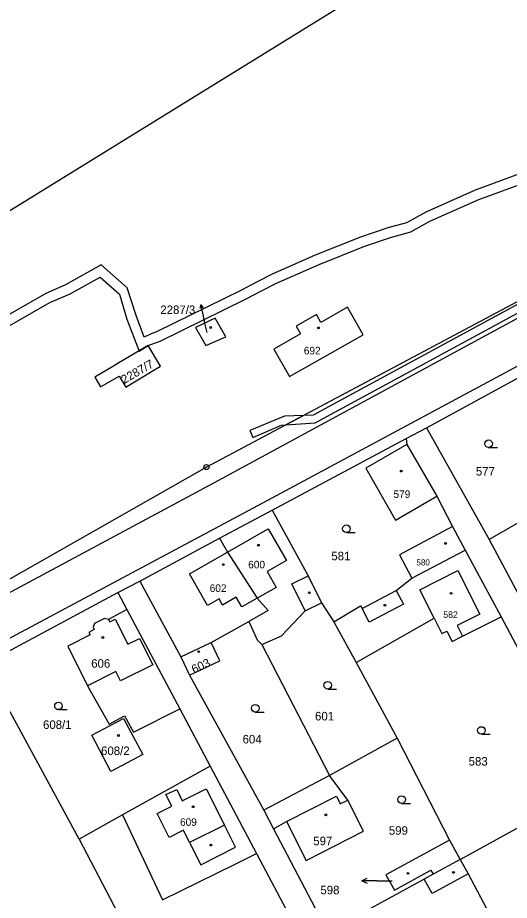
# Model space of a CAD drawing. Extents: x -504988 to -494607, y -1123820 to -1114018.
# Drawn here: x -497680.4 to -497582.5, y -1121208.2 to -1121032.5 of the extents above; entities that cross this region are included whole.
import ezdxf

# ---------------------------------------------------------------- set-up
doc = ezdxf.new("R2010")
doc.units = 0
for name, color, linetype in [('Hranice parcel', 7, 'Continuous'), ('Parcelní čísla', 7, 'Continuous'), ('Pop  PČ popisy', 7, 'Continuous'), ('Vnitřní kresba', 7, 'Continuous'), ('Věcná břemena k části', 7, 'Continuous'), ('Značky bodu BP', 7, 'Continuous'), ('Značky budov', 7, 'Continuous'), ('Značky kultur', 7, 'Continuous')]:
    doc.layers.add(name, color=color, linetype=linetype)

msp = doc.modelspace()

# ---------------------------------------------------------------- linework, layer by layer
at = {"layer": 'Hranice parcel'}
for p, q in [((-497598.99, -1121114.11), (-497574.88, -1121100.96)), ((-497603.06, -1121116.29), (-497598.99, -1121114.11)), ((-497598.99, -1121114.11), (-497586.5, -1121136.34)), ((-497629.69, -1121130.52), (-497603.06, -1121116.29)), ((-497603.06, -1121116.29), (-497602.88, -1121117.43)), ((-497602.88, -1121117.43), (-497596.93, -1121127.76)), ((-497596.93, -1121127.76), (-497593.79, -1121133.79)), ((-497571.04, -1121127.52), (-497586.5, -1121136.34)), ((-497640.18, -1121136.12), (-497629.69, -1121130.52)), ((-497593.79, -1121133.79), (-497591.32, -1121138.45)), ((-497656.09, -1121144.62), (-497640.18, -1121136.12)), ((-497586.5, -1121136.34), (-497579.58, -1121149.32)), ((-497601.88, -1121144.05), (-497591.32, -1121138.45)), ((-497591.32, -1121138.45), (-497584.13, -1121151.76)), ((-497660.42, -1121146.93), (-497656.09, -1121144.62)), ((-497656.09, -1121144.62), (-497647.9, -1121159.74)), ((-497687.08, -1121161.17), (-497660.42, -1121146.93)), ((-497660.42, -1121146.93), (-497658.64, -1121150.29)), ((-497658.64, -1121150.29), (-497648.12, -1121170.07)), ((-497619.86, -1121148.95), (-497617.46, -1121152.74)), ((-497584.13, -1121151.76), (-497566.16, -1121185.61)), ((-497641.85, -1121156.86), (-497634.37, -1121152.67)), ((-497617.46, -1121152.74), (-497613.02, -1121160.87)), ((-497647.9, -1121159.74), (-497641.85, -1121156.86)), ((-497631.8, -1121157.26), (-497618.3, -1121183.34)), ((-497668.13, -1121196.02), (-497687.08, -1121161.17)), ((-497647.9, -1121159.74), (-497646.16, -1121163.39)), ((-497613.02, -1121160.87), (-497604.82, -1121175.88)), ((-497646.16, -1121163.39), (-497631.36, -1121190.24)), ((-497648.12, -1121170.07), (-497642.06, -1121181.45)), ((-497604.82, -1121175.88), (-497618.3, -1121183.34)), ((-497604.82, -1121175.88), (-497594.41, -1121196.17)), ((-497642.06, -1121181.45), (-497659.48, -1121191.18)), ((-497642.06, -1121181.45), (-497632.82, -1121198.83)), ((-497618.3, -1121183.34), (-497631.36, -1121190.24)), ((-497592.3, -1121200.03), (-497566.16, -1121185.61)), ((-497631.36, -1121190.24), (-497629.44, -1121193.91)), ((-497659.48, -1121191.18), (-497668.13, -1121196.02)), ((-497629.44, -1121193.91), (-497618.63, -1121214.47)), ((-497668.13, -1121196.02), (-497656.18, -1121218.8)), ((-497594.41, -1121196.17), (-497592.3, -1121200.03)), ((-497632.82, -1121198.83), (-497623.17, -1121216.97)), ((-497592.3, -1121200.03), (-497597.68, -1121202.98))]:
    msp.add_line(p, q, dxfattribs=at)
for points in [[(-497161, -1120877.53), (-497162.08, -1120875.61), (-497193.91, -1120893.79), (-497205.64, -1120899.19), (-497240.26, -1120919.63), (-497250.18, -1120924.55), (-497404.22, -1121006.98), (-497504.86, -1121061.28), (-497548.64, -1121084.52), (-497630.65, -1121128.6), (-497742.3, -1121188.23), (-497831.7, -1121236.04), (-497830.39, -1121238.19)], [(-497196.93, -1120886.64), (-497265.24, -1120919.02), (-497346.92, -1120963.08), (-497519.27, -1121056.03), (-497550.25, -1121072.74), (-497642.8, -1121121.95), (-497742.1, -1121178.41), (-497789.44, -1121202.25)], [(-497820.06, -1121150.54), (-497737.19, -1121105.25), (-497683.84, -1121072.07), (-497616.03, -1121030.24), (-497577.75, -1121006.29)], [(-497629.38, -1121098.45), (-497626.29, -1121103.91), (-497611.6, -1121095.6), (-497614.69, -1121090.14), (-497620, -1121093.14), (-497620.87, -1121091.61), (-497624.94, -1121093.91), (-497624.07, -1121095.44), (-497629.38, -1121098.45)], [(-497644.95, -1121094.17), (-497642.91, -1121097.78), (-497638.93, -1121096), (-497641.09, -1121092.29), (-497644.95, -1121094.17)], [(-497660.21, -1121101.23), (-497661.29, -1121101.86), (-497664.99, -1121104.02), (-497663.86, -1121105.98), (-497660.16, -1121103.85), (-497658.82, -1121106.02), (-497657.76, -1121105.38), (-497651.95, -1121101.89), (-497654.37, -1121097.77), (-497660.21, -1121101.23)], [(-497602.88, -1121117.43), (-497611.08, -1121122.14), (-497605.13, -1121132.48), (-497596.93, -1121127.76)], [(-497629.69, -1121130.52), (-497622.54, -1121143.56), (-497619.86, -1121148.95)], [(-497593.79, -1121133.79), (-497604.35, -1121139.4), (-497601.88, -1121144.05)], [(-497640.18, -1121136.12), (-497638.63, -1121138.88), (-497632.71, -1121148.04), (-497630.52, -1121150.51), (-497634.37, -1121152.67)], [(-497617.46, -1121152.74), (-497612.12, -1121149.59), (-497611.82, -1121150.07), (-497605.01, -1121146.48), (-497601.88, -1121144.05)], [(-497658.64, -1121150.29), (-497662.28, -1121152.3), (-497663.08, -1121152.07), (-497665.07, -1121153.06), (-497665.36, -1121153.84), (-497665.13, -1121154.3), (-497666.21, -1121154.84), (-497665.95, -1121155.36), (-497670.42, -1121157.6), (-497666.47, -1121165.45), (-497662.16, -1121173.09), (-497659.08, -1121171.46), (-497657.34, -1121174.73), (-497648.12, -1121170.07)], [(-497631.8, -1121157.26), (-497627.84, -1121155.55), (-497623.14, -1121150.58), (-497619.86, -1121148.95)], [(-497613.02, -1121160.87), (-497597.45, -1121152.01), (-497595.92, -1121155.05), (-497594.97, -1121154.57), (-497593.9, -1121156.68), (-497591.79, -1121155.61), (-497584.13, -1121151.76)], [(-497634.37, -1121152.67), (-497632.72, -1121156.31), (-497631.8, -1121157.26)], [(-497646.16, -1121163.39), (-497640.11, -1121160.51), (-497641.85, -1121156.86)], [(-497665.6, -1121175.32), (-497659.29, -1121172.01), (-497655.47, -1121179.17), (-497661.81, -1121182.51), (-497665.6, -1121175.32)], [(-497629.44, -1121193.91), (-497626.87, -1121192.51), (-497622.93, -1121200.24), (-497611.51, -1121194.42), (-497614.68, -1121188.21), (-497618.3, -1121183.34)], [(-497659.48, -1121191.18), (-497651.53, -1121208.08), (-497637.11, -1121200.96), (-497632.82, -1121198.83)], [(-497594.41, -1121196.17), (-497607.08, -1121203.1), (-497605.35, -1121206.15), (-497598.12, -1121202.18), (-497597.68, -1121202.98)], [(-497592.3, -1121200.03), (-497590.72, -1121202.9), (-497586.47, -1121210.95)], [(-497597.68, -1121202.98), (-497599.44, -1121203.94), (-497618.63, -1121214.47)]]:
    msp.add_lwpolyline(points, dxfattribs=at)
at = {"layer": 'Pop  PČ popisy'}
for p, q in [((-497643.91, -1121089.65), (-497644.09, -1121090.38)), ((-497643.46, -1121091.61), (-497643.91, -1121089.65)), ((-497643.91, -1121089.65), (-497643.43, -1121090.23)), ((-497611.83, -1121204.28), (-497610.83, -1121203.78)), ((-497608.83, -1121204.28), (-497611.83, -1121204.28)), ((-497611.83, -1121204.28), (-497610.83, -1121204.78)), ((-497608.83, -1121204.28), (-497605.83, -1121204.28))]:
    msp.add_line(p, q, dxfattribs=at)
msp.add_lwpolyline([(-497642.66, -1121095.14), (-497643.02, -1121093.57), (-497643.46, -1121091.61)], dxfattribs=at)
at = {"layer": 'Vnitřní kresba'}
for p, q in [((-497641.18, -1121124.99), (-497548.12, -1121074.56)), ((-497817.23, -1121219.27), (-497641.18, -1121124.99)), ((-497638.63, -1121138.88), (-497630.49, -1121134.24)), ((-497630.49, -1121134.24), (-497626.89, -1121140.56)), ((-497646.19, -1121143.19), (-497638.63, -1121138.88)), ((-497626.89, -1121140.56), (-497630.71, -1121142.73)), ((-497642.59, -1121149.51), (-497646.19, -1121143.19)), ((-497630.71, -1121142.73), (-497628.92, -1121145.88)), ((-497625.82, -1121145.18), (-497622.54, -1121143.56)), ((-497600.3, -1121146.39), (-497592.74, -1121142.56)), ((-497592.74, -1121142.56), (-497588.36, -1121151.22)), ((-497623.14, -1121150.58), (-497625.82, -1121145.18)), ((-497628.92, -1121145.88), (-497632.71, -1121148.04)), ((-497605.01, -1121146.48), (-497603.56, -1121149.22)), ((-497597.45, -1121152.01), (-497600.3, -1121146.39)), ((-497640.27, -1121148.18), (-497642.59, -1121149.51)), ((-497639.57, -1121149.4), (-497640.27, -1121148.18)), ((-497636.85, -1121147.85), (-497639.57, -1121149.4)), ((-497635.76, -1121149.78), (-497636.85, -1121147.85)), ((-497632.71, -1121148.04), (-497635.76, -1121149.78)), ((-497610.38, -1121152.81), (-497611.82, -1121150.07)), ((-497603.56, -1121149.22), (-497610.38, -1121152.81)), ((-497662.28, -1121152.3), (-497662.05, -1121152.76)), ((-497662.05, -1121152.76), (-497660.95, -1121152.2)), ((-497660.95, -1121152.2), (-497658.43, -1121157.21)), ((-497588.36, -1121151.22), (-497592.86, -1121153.5)), ((-497592.86, -1121153.5), (-497591.79, -1121155.61)), ((-497658.43, -1121157.21), (-497656.11, -1121156.05)), ((-497656.11, -1121156.05), (-497653.47, -1121161.29)), ((-497660.86, -1121162.63), (-497666.47, -1121165.45)), ((-497659.91, -1121164.52), (-497660.86, -1121162.63)), ((-497653.47, -1121161.29), (-497659.91, -1121164.52)), ((-497650.87, -1121187.14), (-497648.71, -1121186.14)), ((-497649.72, -1121189.42), (-497650.87, -1121187.14)), ((-497648.71, -1121186.14), (-497647.6, -1121188.36)), ((-497647.6, -1121188.36), (-497642.82, -1121185.96)), ((-497642.82, -1121185.96), (-497639.2, -1121193.19)), ((-497626.87, -1121192.51), (-497616.92, -1121187.43)), ((-497616.92, -1121187.43), (-497616.15, -1121188.95)), ((-497616.15, -1121188.95), (-497614.68, -1121188.21)), ((-497652.64, -1121190.88), (-497649.72, -1121189.42)), ((-497650.24, -1121195.65), (-497652.64, -1121190.88)), ((-497647.39, -1121194.22), (-497650.24, -1121195.65)), ((-497646.16, -1121196.67), (-497647.39, -1121194.22)), ((-497639.2, -1121193.19), (-497646.16, -1121196.67)), ((-497637, -1121197.6), (-497639.2, -1121193.19)), ((-497646.16, -1121196.67), (-497643.94, -1121201.08)), ((-497643.94, -1121201.08), (-497637, -1121197.6)), ((-497590.72, -1121202.9), (-497597.85, -1121206.84)), ((-497597.85, -1121206.84), (-497599.44, -1121203.94))]:
    msp.add_line(p, q, dxfattribs=at)
at = {"layer": 'Věcná břemena k části'}
for points in [[(-497542.08, -1121022.4), (-497561.97, -1121033.92), (-497552.23, -1121052.81), (-497555.31, -1121053.45), (-497556.45, -1121054.2), (-497558.35, -1121055.16), (-497566.12, -1121057.93), (-497568.73, -1121058.94), (-497575.21, -1121061.24), (-497579.23, -1121063.13), (-497589.3, -1121066.84), (-497599.15, -1121071.19), (-497602.98, -1121073.34), (-497606.71, -1121074.35), (-497612.15, -1121076.17), (-497621.14, -1121079.78), (-497629.68, -1121083.55), (-497632.72, -1121085.08), (-497635.95, -1121086.78), (-497652.77, -1121095.06), (-497653.83, -1121095.42)], [(-497684.34, -1121095.13), (-497673.95, -1121089.18), (-497669.92, -1121087.44), (-497663.94, -1121084.13), (-497660.13, -1121087.52), (-497658.66, -1121092.53), (-497656.21, -1121098.86), (-497654.37, -1121097.77), (-497653.11, -1121097.29), (-497652, -1121096.9), (-497635.03, -1121088.56), (-497631.81, -1121086.87), (-497628.85, -1121085.37), (-497620.38, -1121081.63), (-497611.49, -1121078.06), (-497606.15, -1121076.27), (-497602.11, -1121075.14), (-497598.29, -1121073), (-497588.58, -1121068.71), (-497578.42, -1121064.96)], [(-497653.83, -1121095.42), (-497655.17, -1121096.09), (-497656.79, -1121091.81), (-497658.56, -1121086.27), (-497663.73, -1121081.71), (-497670.85, -1121085.67), (-497674.79, -1121087.37), (-497685.25, -1121093.36), (-497691.54, -1121096.24), (-497696.32, -1121097.73), (-497705.29, -1121102.06), (-497742.66, -1121121.92), (-497743.02, -1121122.93), (-497744.98, -1121123.46), (-497747.81, -1121124.56), (-497775.29, -1121138.97), (-497812.1, -1121159.16), (-497814.23, -1121160.38)]]:
    msp.add_lwpolyline(points, dxfattribs=at)
for points in [[(-497563.03, -1121079.92), (-497621.52, -1121111.63), (-497623.49, -1121111.68), (-497627.01, -1121113.55), (-497621.12, -1121113.12), (-497563.61, -1121081.94), (-497563.17, -1121082.72), (-497559.01, -1121090.09), (-497557.95, -1121091.97), (-497556.63, -1121091.26), (-497557.69, -1121089.38), (-497561.85, -1121082)], [(-497634.13, -1121114.65), (-497633.56, -1121116.04), (-497627.87, -1121113.62), (-497627.01, -1121113.55), (-497623.49, -1121111.68), (-497627.25, -1121111.79)]]:
    msp.add_lwpolyline(points, close=True, dxfattribs=at)
at = {"layer": 'Značky bodu BP'}
for radius in [0.5, 0.0303]:
    msp.add_circle((-497642.8, -1121121.95), radius, dxfattribs=at)
at = {"layer": 'Značky budov'}
for centre in [(-497641.95, -1121094.17), (-497620.5, -1121094.25), (-497604.01, -1121122.75), (-497632.45, -1121137.51), (-497595.19, -1121137.14), (-497639.44, -1121141.35), (-497622.32, -1121146.96), (-497594.09, -1121147.07), (-497607.26, -1121149.44), (-497663.43, -1121155.87), (-497644.35, -1121158.68), (-497660.32, -1121175.37), (-497645.45, -1121189.54), (-497619.01, -1121191.16), (-497641.93, -1121197.18), (-497602.66, -1121202.81), (-497593.61, -1121202.62)]:
    msp.add_circle(centre, 0.175, dxfattribs=at)
at = {"layer": 'Značky kultur'}
for p, q in [((-497586.62, -1121118.05), (-497584.87, -1121118.05)), ((-497614.94, -1121134.97), (-497613.19, -1121134.97)), ((-497618.65, -1121166.12), (-497616.9, -1121166.12)), ((-497672.26, -1121170.22), (-497670.51, -1121170.22)), ((-497633.07, -1121170.7), (-497631.32, -1121170.7)), ((-497588.05, -1121175.11), (-497586.3, -1121175.11)), ((-497603.94, -1121188.87), (-497602.19, -1121188.87))]:
    msp.add_line(p, q, dxfattribs=at)
for centre in [(-497586.62, -1121117.3), (-497614.94, -1121134.22), (-497618.65, -1121165.37), (-497672.26, -1121169.47), (-497633.07, -1121169.95), (-497588.05, -1121174.36), (-497603.94, -1121188.12)]:
    msp.add_circle(centre, 0.75, dxfattribs=at)

# ---------------------------------------------------------------- texts
at = {"layer": 'Parcelní čísla'}
for s, height, p in [('2287/3', 1.7, (-497651.98, -1121091.49)), ('692', 1.5, (-497623.41, -1121099.52)), ('577', 1.7, (-497589.16, -1121123.63)), ('579', 1.5, (-497605.56, -1121128.08)), ('581', 1.7, (-497617.93, -1121140.49)), ('600', 1.5, (-497634.48, -1121142.1)), ('580', 1.2, (-497600.99, -1121141.52)), ('602', 1.5, (-497642.15, -1121146.79)), ('582', 1.3, (-497595.64, -1121151.97)), ('606', 1.7, (-497665.74, -1121161.88)), ('601', 1.7, (-497621.18, -1121172.37)), ('608/1', 1.7, (-497675.33, -1121174.06)), ('604', 1.7, (-497635.6, -1121176.95)), ('608/2', 1.7, (-497663.78, -1121179.26)), ('583', 1.7, (-497590.59, -1121181.36)), ('609', 1.5, (-497648.06, -1121193.35)), ('599', 1.7, (-497606.48, -1121195.12)), ('597', 1.7, (-497621.53, -1121197.21)), ('598', 1.7, (-497620.11, -1121206.97))]:
    msp.add_text(s, height=height, dxfattribs=at).set_placement(p)
for s, rotation, p in [('2287/7', 30, (-497659.16, -1121105.42)), ('603', 25, (-497645.28, -1121163.08))]:
    msp.add_text(s, height=1.7, rotation=rotation, dxfattribs=at).set_placement(p)

doc.saveas('drawing.dxf')
